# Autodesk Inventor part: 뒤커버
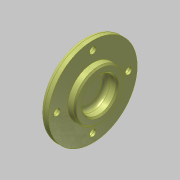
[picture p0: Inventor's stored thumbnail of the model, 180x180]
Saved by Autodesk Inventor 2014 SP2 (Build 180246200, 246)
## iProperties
Created: 2015-12
Part Number: 뒤커버
Document SubType Name: Modeling
Designer: mdu
Density: 2.71 g/cm^3
Material: 알루미늄 6061
Mass: 56.1988 g
Surface Area: 84.0425 cm^2
Volume: 20.7376 cm^3
Appearance: 알루미늄 - 평지
Author: mdu
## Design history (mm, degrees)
sketch "스케치1"
  geometry: L1 (-7, 0)-(7, 0); L2 (-7, 0)-(-7, 15.539); L3 (-7, 15.539)-(-4, 18.5); L4 (-4, 18.5)-(-4, 31); L5 (-4, 31)-(2, 31); L6 (2, 31)-(2, 17.5); L7 (2, 17.5)-(7, 17.5); L8 (7, 17.5)-(7, 0); 2 further points
  constraints: 16 end point, 4 parallel, 2 perpendicular, 1 coincident, 1 horizontal, 1 midpoint
  dimensions: "d0" = 14 distance of L1.start L1.end; "d1" = 62 diameter of L5 L1; "d2" = 35 diameter of L7 L1; "d3" = 37 diameter of L3.end L1; "d4" = 3 distance between parallel lines of L4 L2; "d5" = 6 distance of L4.end L5.end
revolve "회전1" sketch "스케치1" stored, may be unused: angle "d6" = 90 deg
sketch "스케치2" dims "d32" = 50
  geometry: 3 further points
  constraints: 2 vertical alignment, 1 coincident, 2 other
hole "구멍1" sketch "스케치2" at (0, 25) diameter "d8" = 4.5; stored, may be unused: countersink angle "d12" = 90 deg, drill point angle "d14" = 118 deg; dims "d9" = 6, "d10" = 8, "d11" = 4.4, "d13" = 8
hole "구멍2" diameter "d20" = 24; stored, may be unused: countersink angle "d24" = 90 deg, drill point angle "d26" = 0 deg; dims "d18" = 10, "d19" = 10, "d21" = 6, "d22" = 8, "d23" = 4.4, "d25" = 8
fillet "모깎기1" dims "d27" = 3
fillet "모깎기2" dims "d28" = 3
chamfer "모따기1" distance "d29" = 1; stored, may be unused: second distance "d30" = 2, angle "d31" = 45 deg
node "솔리드1"
pattern_circular "원형 패턴1" dims angle "d16" = 360 deg
